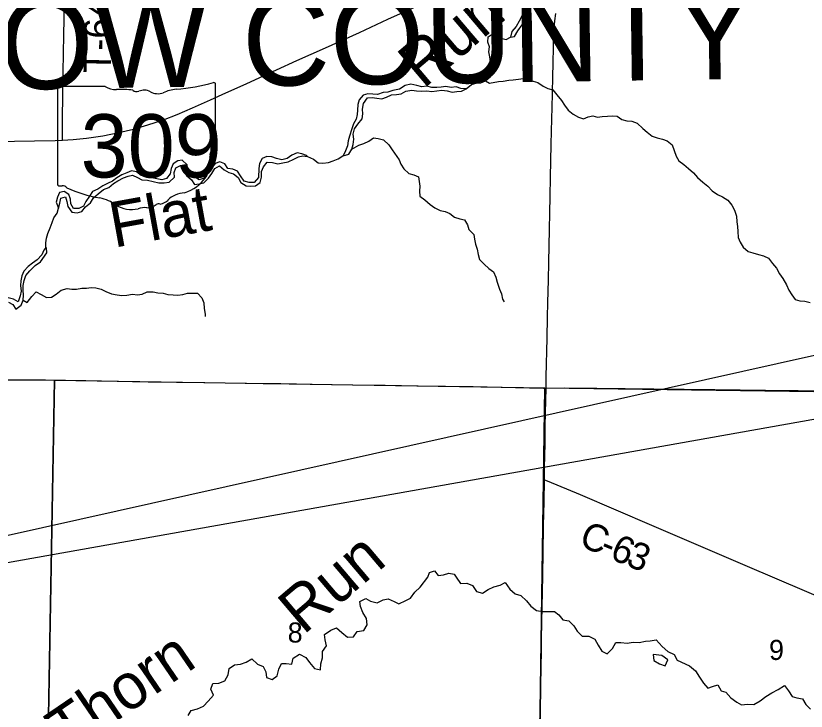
# Model space of a CAD drawing. Extents: x 0 to 45.9, y 0 to 22.
# Drawn here: x 6.459 to 8.107, y 18.033 to 19.483 of the extents above; entities that cross this region are included whole.
import ezdxf

# ---------------------------------------------------------------- set-up
doc = ezdxf.new("R2010")
doc.units = 0
for name, color, linetype in [('GM_X_County_Road', 7, 'Continuous'), ('GM_X_County_Road_Text', 7, 'Continuous'), ('GM_X_County_Text', 7, 'Continuous'), ('GM_X_Minor_Lake', 7, 'Continuous'), ('GM_X_Minor_River', 7, 'Continuous'), ('GM_X_Minor_River_Text', 7, 'Continuous'), ('GM_X_Section', 7, 'Continuous'), ('GM_X_Section_Text', 7, 'Continuous'), ('GM_X_State_Location', 7, 'Continuous'), ('GM_X_State_Route', 7, 'Continuous'), ('GM_X_State_Shield', 7, 'Continuous'), ('GM_X_Township_Road', 7, 'Continuous'), ('GM_X_Township_Road_Text', 7, 'Continuous'), ('SH_Border', 7, 'Continuous')]:
    doc.layers.add(name, color=color, linetype=linetype)

msp = doc.modelspace()

# ---------------------------------------------------------------- linework, layer by layer
at = {"layer": 'GM_X_County_Road'}
for points in [[(7.5646, 18.7065), (7.5647, 18.7113), (7.5647, 18.73), (7.5668, 18.8107), (7.5676, 18.8542), (7.5681, 18.8852), (7.5693, 18.9318), (7.5702, 18.9691), (7.571, 19.0032), (7.5733, 19.1058), (7.574, 19.1461), (7.5745, 19.1803), (7.5753, 19.2145), (7.576, 19.2424), (7.5772, 19.2921), (7.5777, 19.3201), (7.5783, 19.3575), (7.5793, 19.3821), (7.5801, 19.4194), (7.5807, 19.4411), (7.5814, 19.4566), (7.5828, 19.4721), (7.5847, 19.4875)], [(6.2851, 18.7249), (6.3844, 18.7247), (6.5212, 18.7234), (6.6051, 18.7221), (6.7354, 18.7198), (6.8535, 18.7178), (6.9374, 18.7166), (6.9747, 18.7162), (7.012, 18.7157), (7.0772, 18.7145), (7.1611, 18.7135), (7.2295, 18.7125), (7.2979, 18.7112), (7.4129, 18.7096), (7.5589, 18.7064), (7.5646, 18.7065)], [(7.5612, 18.5152), (7.5616, 18.5404), (7.5628, 18.5901), (7.563, 18.6276), (7.5642, 18.6807), (7.5646, 18.7065)], [(7.5646, 18.7065), (7.6024, 18.707), (7.6707, 18.7061), (7.7889, 18.705), (7.9163, 18.7034), (8.0219, 18.7023), (8.0903, 18.7015), (8.1929, 18.7), (8.2363, 18.6995), (8.3078, 18.6991), (8.4353, 18.6974), (8.4943, 18.6963), (8.5313, 18.6958)], [(7.5458, 17.698), (7.5463, 17.7142), (7.5476, 17.7856), (7.5486, 17.8446), (7.5508, 17.9503), (7.5522, 18.0404), (7.5541, 18.1211), (7.5547, 18.1615), (7.5549, 18.1832), (7.5556, 18.2174), (7.5564, 18.2516), (7.557, 18.2795), (7.5577, 18.3168), (7.5585, 18.3633), (7.5593, 18.4193), (7.5603, 18.469), (7.5612, 18.5152)], [(7.5612, 18.5152), (7.5666, 18.5129), (7.6355, 18.4843), (7.7843, 18.4208), (7.9787, 18.3375), (8.1074, 18.2827), (8.1417, 18.268), (8.2218, 18.2337), (8.296, 18.2014), (8.3105, 18.1959), (8.3195, 18.1935), (8.3287, 18.192), (8.3442, 18.191), (8.4873, 18.1896), (8.5278, 18.189), (8.5332, 18.1889)]]:
    msp.add_lwpolyline(points, dxfattribs=at)
at = {"layer": 'GM_X_Minor_Lake'}
for points in [[(7.7875, 18.1513), (7.789, 18.1384), (7.8008, 18.1313), (7.813, 18.1275), (7.8157, 18.1337)], [(7.8157, 18.1337), (7.8186, 18.1401), (7.8061, 18.1487), (7.7875, 18.1513)]]:
    msp.add_lwpolyline(points, dxfattribs=at)
at = {"layer": 'GM_X_Minor_River'}
for points in [[(7.5153, 19.4844), (7.5085, 19.4713), (7.5022, 19.4605), (7.4935, 19.4497), (7.4902, 19.438)], [(7.4902, 19.438), (7.4986, 19.4397), (7.5057, 19.4512), (7.5144, 19.4635), (7.5196, 19.4733), (7.5263, 19.4837)], [(7.3978, 19.3304), (7.4091, 19.3396), (7.419, 19.3424), (7.4285, 19.3428), (7.4381, 19.3468), (7.4485, 19.3563), (7.4507, 19.3665), (7.4522, 19.3775), (7.449, 19.3875), (7.4474, 19.397), (7.445, 19.4073), (7.4465, 19.4179), (7.4429, 19.4275), (7.4436, 19.4389), (7.4541, 19.4458), (7.4639, 19.4467), (7.4704, 19.4363), (7.4813, 19.4333), (7.4902, 19.438)], [(7.4381, 19.3468), (7.4466, 19.342), (7.4657, 19.346), (7.4752, 19.3465), (7.4866, 19.3485), (7.4961, 19.3489), (7.5071, 19.3505), (7.5166, 19.3518), (7.5275, 19.3504), (7.5377, 19.3467), (7.5474, 19.3437), (7.5582, 19.3358), (7.5683, 19.331), (7.5784, 19.3284), (7.5868, 19.3176), (7.5964, 19.3063), (7.6033, 19.2966), (7.6106, 19.2857), (7.6213, 19.2775), (7.6318, 19.2711), (7.6426, 19.2678), (7.6522, 19.2721), (7.6618, 19.2744), (7.6719, 19.2711), (7.6814, 19.2728), (7.6928, 19.2736), (7.7023, 19.2741), (7.7125, 19.2734), (7.7225, 19.2663), (7.7327, 19.2637), (7.7436, 19.2627), (7.7545, 19.259), (7.7659, 19.248), (7.7756, 19.2401), (7.7856, 19.2319), (7.7961, 19.2285), (7.8073, 19.2256), (7.8171, 19.2223), (7.8271, 19.2136), (7.8313, 19.2017), (7.8359, 19.1902), (7.8413, 19.1806), (7.8517, 19.1727), (7.8613, 19.1644), (7.8717, 19.1554), (7.8805, 19.1457), (7.8916, 19.1355), (7.9016, 19.1272), (7.9108, 19.1175), (7.9219, 19.11), (7.9324, 19.1051), (7.9432, 19.098), (7.9516, 19.0879), (7.9574, 19.0774), (7.9612, 19.0652), (7.9624, 19.0534), (7.9633, 19.0435), (7.9645, 19.0328), (7.9649, 19.0203), (7.9688, 19.0106), (7.9753, 19.0006), (7.9857, 18.9912), (7.9955, 18.9886), (8.0075, 18.9853), (8.0176, 18.9823), (8.0281, 18.9771), (8.0365, 18.9662), (8.0446, 18.9565), (8.051, 18.9445), (8.058, 18.9349), (8.0659, 18.9217), (8.0709, 18.9109), (8.0767, 18.9009), (8.084, 18.8912), (8.0938, 18.8887), (8.104, 18.8876), (8.1153, 18.8846)], [(7.3978, 19.3304), (7.3869, 19.3311), (7.3771, 19.3344), (7.3669, 19.3335), (7.3559, 19.335), (7.3461, 19.3337), (7.3366, 19.3329), (7.3267, 19.3331), (7.3158, 19.3361), (7.3059, 19.3349), (7.295, 19.3371), (7.2826, 19.3401), (7.2708, 19.3373), (7.2588, 19.3297), (7.2451, 19.3267), (7.2344, 19.3235), (7.225, 19.323), (7.2135, 19.3188), (7.2033, 19.3195), (7.1931, 19.3201), (7.1831, 19.3174), (7.1753, 19.3077), (7.1724, 19.2979), (7.1713, 19.2862), (7.1706, 19.2767), (7.1685, 19.2669), (7.1629, 19.2572), (7.16, 19.247), (7.155, 19.2315), (7.1521, 19.2217), (7.1507, 19.2115), (7.1462, 19.201), (7.1418, 19.1909)], [(7.1418, 19.1909), (7.1536, 19.194), (7.1596, 19.2044), (7.1625, 19.2146), (7.1639, 19.2256), (7.1627, 19.2359), (7.1653, 19.2468), (7.172, 19.2569), (7.1814, 19.268), (7.1824, 19.2783), (7.182, 19.2882), (7.1842, 19.2995), (7.1921, 19.3118), (7.2019, 19.3123), (7.2117, 19.3109), (7.2219, 19.3098), (7.2322, 19.313), (7.2426, 19.318), (7.2525, 19.3185), (7.2624, 19.3201), (7.2723, 19.3252), (7.2845, 19.3279), (7.2947, 19.326), (7.3057, 19.3257), (7.3159, 19.3262), (7.3265, 19.3248), (7.3371, 19.3264), (7.3474, 19.3276), (7.3583, 19.3262), (7.3689, 19.3236), (7.3788, 19.3249), (7.3882, 19.3254), (7.3978, 19.3304)], [(7.1596, 19.2044), (7.1742, 19.2132), (7.1845, 19.2167), (7.1949, 19.2213), (7.2045, 19.2279), (7.2147, 19.2268), (7.2256, 19.2239), (7.2367, 19.2133), (7.2436, 19.2029), (7.2582, 19.1827), (7.2621, 19.1731), (7.2683, 19.1634), (7.2782, 19.1537), (7.2887, 19.1511), (7.2988, 19.1466), (7.3001, 19.1371), (7.3013, 19.1272), (7.3007, 19.117), (7.3015, 19.1067), (7.3119, 19.0992), (7.323, 19.089), (7.333, 19.0823), (7.3435, 19.077), (7.354, 19.0748), (7.3642, 19.0704), (7.3738, 19.0629), (7.3847, 19.0595), (7.3948, 19.057), (7.4006, 19.0469), (7.4037, 19.037), (7.4141, 19.0268), (7.4153, 19.0169), (7.4177, 19.0066), (7.4208, 18.9959), (7.4231, 18.9852), (7.4259, 18.9745), (7.4355, 18.9647), (7.4451, 18.9561), (7.4547, 18.949), (7.4597, 18.9374), (7.4628, 18.9271), (7.4674, 18.9129), (7.4713, 18.9033), (7.4736, 18.8922), (7.4772, 18.8864)], [(7.0675, 19.1895), (7.0649, 19.1911), (7.0552, 19.1952), (7.0454, 19.197), (7.0346, 19.192), (7.025, 19.1854), (7.0139, 19.1827), (7.003, 19.1852), (6.9932, 19.1885), (6.9827, 19.1892), (6.9727, 19.1853), (6.9675, 19.1744), (6.9657, 19.1646), (6.9652, 19.1453), (6.9558, 19.1353), (6.9459, 19.1348), (6.9354, 19.1381), (6.9274, 19.149), (6.9212, 19.1586), (6.9115, 19.1627), (6.9013, 19.1641), (6.8951, 19.1738), (6.8846, 19.1779), (6.8751, 19.1747), (6.8669, 19.1651), (6.8519, 19.1442), (6.8416, 19.1407), (6.8315, 19.1467), (6.8218, 19.1523), (6.8149, 19.162), (6.8163, 19.1718), (6.8063, 19.1816), (6.7968, 19.1803), (6.7872, 19.1741), (6.7828, 19.164), (6.7813, 19.1534), (6.7731, 19.1437), (6.7636, 19.141), (6.7425, 19.1446), (6.7316, 19.1476), (6.7206, 19.1498), (6.7106, 19.1576), (6.7004, 19.1591), (6.6909, 19.1551), (6.6801, 19.1509), (6.6701, 19.1451), (6.6605, 19.1381), (6.6505, 19.1331), (6.6409, 19.1284), (6.6301, 19.1215), (6.6194, 19.1165), (6.613, 19.1068), (6.6055, 19.0956), (6.6007, 19.0858), (6.5903, 19.0808), (6.5797, 19.0811), (6.5743, 19.0908), (6.5731, 19.1003), (6.5696, 19.1099), (6.5599, 19.1162), (6.5504, 19.1142), (6.5459, 19.1045), (6.5434, 19.0943), (6.5483, 19.0816)], [(6.5483, 19.0816), (6.5509, 19.0922), (6.5534, 19.1023), (6.563, 19.1055), (6.5657, 19.0952), (6.5677, 19.0849), (6.5761, 19.0736), (6.5871, 19.0718), (6.5966, 19.0746), (6.6044, 19.0842), (6.6149, 19.0927), (6.6209, 19.1031), (6.6306, 19.1116), (6.6422, 19.1204), (6.6529, 19.125), (6.6626, 19.1331), (6.6722, 19.1389), (6.6834, 19.1447), (6.6933, 19.1482), (6.7028, 19.1503), (6.7126, 19.1458), (6.7223, 19.1406), (6.7336, 19.1399), (6.7457, 19.1369), (6.7577, 19.1343), (6.7683, 19.1344), (6.779, 19.136), (6.7898, 19.1459), (6.7897, 19.1562), (6.7927, 19.166), (6.8026, 19.1703), (6.8095, 19.1595), (6.8153, 19.1498), (6.8257, 19.1408), (6.8318, 19.1311), (6.8417, 19.1323), (6.8512, 19.1344), (6.8606, 19.1444), (6.8677, 19.154), (6.874, 19.1641), (6.884, 19.1699), (6.8937, 19.1613), (6.9033, 19.1557), (6.9131, 19.1535), (6.9228, 19.1457), (6.9285, 19.1349), (6.9393, 19.1281), (6.9491, 19.1275), (6.959, 19.1283), (6.9687, 19.1349), (6.9712, 19.1459), (6.9712, 19.158), (6.9756, 19.1681), (6.9835, 19.1778), (6.9944, 19.1771), (7.0053, 19.1742), (7.0156, 19.1758), (7.0267, 19.1781), (7.0386, 19.1839), (7.0482, 19.1885), (7.0577, 19.1909), (7.0675, 19.1895)], [(7.0675, 19.1895), (7.0795, 19.1835), (7.0895, 19.1764), (7.0993, 19.1753), (7.1107, 19.1766), (7.1207, 19.1805), (7.131, 19.1843), (7.1406, 19.1909), (7.1418, 19.1909)], [(6.5218, 18.9995), (6.5221, 19.0094), (6.5231, 19.0192), (6.526, 19.029), (6.5309, 19.0403), (6.535, 19.0516), (6.5387, 19.0614), (6.5454, 19.0714), (6.5483, 19.0816)], [(6.5218, 18.9995), (6.5179, 18.9939), (6.5138, 18.9842), (6.5041, 18.9742), (6.4944, 18.9672), (6.4847, 18.9599), (6.4758, 18.9503), (6.4721, 18.9405), (6.4699, 18.9303), (6.4689, 18.9201), (6.4701, 18.9087), (6.4687, 18.8988), (6.4642, 18.8864), (6.4545, 18.892), (6.4436, 18.8946), (6.4328, 18.8907), (6.4214, 18.8868), (6.4102, 18.8928)], [(6.4437, 18.8858), (6.4534, 18.881), (6.4596, 18.8713), (6.4704, 18.8794), (6.4749, 18.8899), (6.4755, 18.9005), (6.4747, 18.9108), (6.4749, 18.9203), (6.4764, 18.9309), (6.4801, 18.941), (6.4887, 18.9507), (6.4999, 18.9618), (6.5108, 18.9694), (6.5242, 18.9888), (6.5233, 18.9987), (6.5218, 18.9995)], [(6.4749, 18.8899), (6.4831, 18.8851), (6.4925, 18.8974), (6.5019, 18.9074), (6.5119, 18.9014), (6.5231, 18.895), (6.5337, 18.8959), (6.5434, 18.9024), (6.5535, 18.9109), (6.5664, 18.9143), (6.5762, 18.9129), (6.5861, 18.913), (6.5971, 18.9146), (6.6066, 18.9151), (6.6161, 18.9164), (6.6263, 18.9157), (6.6372, 18.9128), (6.6469, 18.9075), (6.6589, 18.903), (6.6702, 18.9008), (6.6804, 18.8994), (6.6906, 18.9003), (6.7028, 18.9026), (6.7126, 18.9008), (6.7225, 18.902), (6.7329, 18.9074), (6.7457, 18.9071), (6.7555, 18.9053), (6.7661, 18.9042), (6.7759, 18.9013), (6.7872, 18.9006), (6.7971, 18.9004), (6.8077, 18.9016), (6.8172, 18.9044), (6.8279, 18.9044), (6.8377, 18.9042), (6.8473, 18.8948), (6.8512, 18.8844), (6.852, 18.8722), (6.8543, 18.8608), (6.8542, 18.8558)], [(7.318, 18.3124), (7.3219, 18.3221), (7.3322, 18.3252), (7.3399, 18.3155), (7.3505, 18.3171), (7.362, 18.3206), (7.3729, 18.3188), (7.3772, 18.3121)], [(7.1629, 18.1879), (7.1709, 18.1993), (7.1845, 18.2009), (7.1917, 18.2131), (7.1905, 18.2263), (7.1825, 18.2388), (7.1779, 18.2509), (7.1763, 18.2612), (7.1888, 18.268), (7.1987, 18.2624), (7.2124, 18.259), (7.2253, 18.2651), (7.2351, 18.2671), (7.248, 18.2618), (7.2579, 18.2565), (7.2719, 18.2638), (7.2818, 18.2687), (7.2912, 18.2809), (7.3018, 18.2912), (7.318, 18.3124)], [(7.3772, 18.3121), (7.386, 18.2987), (7.3996, 18.2995), (7.4114, 18.2946), (7.4194, 18.2825), (7.432, 18.2787), (7.4437, 18.2867), (7.4558, 18.2924), (7.4687, 18.2955), (7.4793, 18.3012), (7.4892, 18.2873), (7.4999, 18.2778), (7.512, 18.2741), (7.5238, 18.2631), (7.5326, 18.2521), (7.5444, 18.2427), (7.558, 18.2408), (7.5819, 18.2409), (7.5914, 18.2334), (7.5994, 18.2235), (7.612, 18.2213), (7.6226, 18.2107), (7.6295, 18.1994), (7.6401, 18.1895), (7.6538, 18.1892), (7.666, 18.1828), (7.6732, 18.1707), (7.6808, 18.1578), (7.6922, 18.1525), (7.7032, 18.1636), (7.71, 18.1761), (7.7206, 18.1758), (7.7339, 18.1743), (7.7464, 18.177), (7.7585, 18.1759), (7.7718, 18.179), (7.7817, 18.1794), (7.7942, 18.1813), (7.8067, 18.1677), (7.8182, 18.1571), (7.8315, 18.1507), (7.838, 18.139), (7.8638, 18.1277), (7.876, 18.1167), (7.8847, 18.1039), (7.8924, 18.091), (7.9015, 18.0808), (7.9117, 18.0846), (7.9223, 18.0877), (7.9292, 18.0752), (7.9391, 18.0722), (7.9498, 18.0605), (7.9623, 18.0514), (7.9718, 18.0458), (7.9847, 18.0477), (7.9976, 18.047), (8.0108, 18.0546), (8.0226, 18.0634), (8.0354, 18.0714), (8.0483, 18.0782), (8.0612, 18.0866), (8.0699, 18.0753), (8.0776, 18.0632), (8.0871, 18.0605), (8.0992, 18.0587), (8.1057, 18.047), (8.116, 18.0371)], [(6.8183, 18.024), (6.8251, 18.0343), (6.838, 18.0374), (6.8505, 18.0431), (6.8603, 18.0534), (6.8713, 18.0659), (6.8655, 18.0788), (6.8697, 18.0902), (6.8826, 18.0914), (6.8947, 18.096), (6.9018, 18.1089), (6.9037, 18.1218), (6.915, 18.1298), (6.9276, 18.1306), (6.9397, 18.1352), (6.951, 18.1417), (6.9628, 18.1307), (6.975, 18.1262), (6.9807, 18.1152), (6.9815, 18.1027), (6.9933, 18.0986), (7.0039, 18.1066), (7.0073, 18.1203), (7.0129, 18.132), (7.0228, 18.1321), (7.0349, 18.1306), (7.0375, 18.1431), (7.0508, 18.1519), (7.0637, 18.1447), (7.0717, 18.1341), (7.082, 18.1217), (7.0945, 18.1187), (7.0949, 18.1316), (7.0982, 18.1441), (7.0986, 18.157), (7.1069, 18.1692), (7.1038, 18.1813), (7.103, 18.193), (7.1162, 18.2014), (7.128, 18.2068), (7.139, 18.1966), (7.1508, 18.1871), (7.1629, 18.1879)]]:
    msp.add_lwpolyline(points, dxfattribs=at)
at = {"layer": 'GM_X_Section'}
for points in [[(5.4871, 18.7066), (6.0626, 18.725), (6.54, 18.7231), (6.5217, 17.7114), (6.0871, 17.7131), (5.4835, 17.7031)], [(6.54, 18.7231), (7.5622, 18.7071), (7.5472, 17.6966), (6.5217, 17.7114)], [(7.5622, 18.7071), (8.5306, 18.6937), (8.5357, 17.6824), (7.5472, 17.6966)]]:
    msp.add_lwpolyline(points, close=True, dxfattribs=at)
at = {"layer": 'GM_X_State_Route'}
for points in [[(6.8649, 19.3074), (6.8896, 19.3186), (6.9406, 19.3416), (7.0029, 19.3699), (7.0452, 19.3894), (7.1047, 19.4162), (7.1755, 19.4482), (7.2349, 19.4754), (7.3, 19.505), (7.399, 19.55), (7.4519, 19.5741)], [(6.2899, 19.2184), (6.498, 19.2217), (6.5415, 19.2227), (6.5563, 19.2235), (6.5788, 19.2247), (6.6067, 19.2276), (6.6405, 19.2326), (6.6742, 19.2391), (6.7044, 19.2463), (6.7343, 19.255), (6.7668, 19.2657), (6.7959, 19.2768), (6.8273, 19.2905), (6.8649, 19.3074)]]:
    msp.add_lwpolyline(points, dxfattribs=at)
at = {"layer": 'GM_X_State_Shield'}
for p, q in [((6.5459, 19.3316), (6.5459, 19.1315)), ((6.6457, 19.335), (6.5492, 19.335)), ((6.8755, 19.2353), (6.8755, 19.34)), ((6.8755, 19.2353), (6.8755, 19.2353))]:
    msp.add_line(p, q, dxfattribs=at)
for centre, major_axis, start_param, end_param in [((6.7581, 19.6079), (0.3495, 0), 4.814394, 5.042369), ((6.8719, 19.3404), (0.00367, 0), 6.141152, 7.989035), ((6.5497, 19.332), (0.00382, 0), 1.712693, 3.28349), ((6.6687, 19.3583), (0.037, 0), 4.042523, 4.731795), ((6.681, 19.2227), (0.133, 0), 1.404758, 1.657858), ((6.7111, 19.3331), (0.0107, 0), 3.836095, 5.185415), ((6.7268, 19.3099), (0.0222, 0), 0.950623, 2.079405), ((6.8027, 19.2739), (0.0703, 0), 1.699011, 2.107814), ((6.7555, 19.3416), (0.0267, 0), 4.081561, 5.145723), ((6.8747, 19.2276), (0.00568, 0), 1.883978, 3.671073), ((6.8716, 19.2349), (0.00393, 0), 5.05454, 6.418171), ((6.8385, 19.2144), (0.0341, 0), 5.934695, 6.695948), ((6.8887, 19.1915), (0.0248, 0), 2.387724, 3.262537), ((6.7777, 19.1782), (0.0874, 0), 5.101752, 6.440018), ((6.5497, 19.131), (0.00385, 0), 3.00124, 4.508301), ((6.5503, 19.1515), (0.0294, 0), 4.665946, 4.897461), ((6.5563, 19.1199), (0.0106, 0), 0.519207, 1.627899), ((6.6902, 19.2997), (0.2524, 0), 4.195997, 4.488961), ((6.8145, 19.0753), (0.0479, 0), 1.647645, 2.488434), ((6.6149, 19.0416), (0.079, 0), 0.823519, 1.323587), ((6.7539, 19.1121), (0.0282, 0), 4.937069, 5.64225), ((6.7003, 19.1189), (0.0501, 0), 4.026481, 4.996735), ((6.7293, 19.0497), (0.0412, 0), 1.495662, 1.94098), ((6.7329, 19.1039), (0.0267, 0), 4.691044, 5.507374), ((6.7571, 19.0846), (0.00752, 0), 1.147584, 2.315152)]:
    msp.add_ellipse(centre, major_axis=major_axis, ratio=0.8, start_param=start_param, end_param=end_param, dxfattribs=at)
at = {"layer": 'GM_X_Township_Road'}
msp.add_lwpolyline([(6.5563, 19.2235), (6.5564, 19.2318), (6.5569, 19.2753), (6.5572, 19.3094), (6.5581, 19.3654), (6.5593, 19.443), (6.5605, 19.5082), (6.5618, 19.5859), (6.5633, 19.6636), (6.5655, 19.7101), (6.5652, 19.7172), (6.5649, 19.7189), (6.5645, 19.721), (6.564, 19.7226), (6.5634, 19.724)], dxfattribs=at)
at = {"layer": 'SH_Border'}
msp.add_lwpolyline([(9.5057, 19.0827), (5.2104, 18.1241), (9.5057, 18.8875)], close=True, dxfattribs=at)

# ---------------------------------------------------------------- texts
at = {"layer": 'GM_X_County_Road_Text'}
for s, rotation, p in [('C', 336.8562, (7.6305, 18.3792)), ('6', 337.0732, (7.6951, 18.3516)), ('3', 338.0091, (7.7283, 18.3376)), ('-', 336.8964, (7.6735, 18.3609))]:
    msp.add_text(s, height=0.0568, rotation=rotation, dxfattribs=at).set_placement(p)
at = {"layer": 'GM_X_County_Text'}
msp.add_text('MORROW COUNTY', height=0.189394, rotation=0.8203, dxfattribs=at).set_placement((5.6522, 19.3177))
at = {"layer": 'GM_X_Minor_River_Text'}
for s, rotation, p in [('Run', 40.3114, (7.3085, 19.3288)), ('Flat', 10.3153, (6.6638, 18.9989)), ('Run', 40.3115, (7.0586, 18.1905)), ('Thorn', 34.3127, (6.5666, 17.9416))]:
    msp.add_text(s, height=0.09472, rotation=rotation, dxfattribs=at).set_placement(p)
at = {"layer": 'GM_X_Section_Text'}
for s, p in [('8', (7.026, 18.1759)), ('9', (8.0293, 18.1396))]:
    msp.add_text(s, height=0.0419, rotation=0, dxfattribs=at).set_placement(p)
at = {"layer": 'GM_X_State_Location'}
for s in ['s', 'r']:
    msp.add_text(s, height=0.000189, dxfattribs=at).set_placement((6.707, 19.2182))
msp.add_text('309', height=0.000189, rotation=0, dxfattribs=at).set_placement((6.6402, 19.2044))
at = {"layer": 'GM_X_State_Shield'}
msp.add_text('309', height=0.13184, dxfattribs=at).set_placement((6.5944, 19.1456))
at = {"layer": 'GM_X_Township_Road_Text'}
msp.add_text('T-64', height=0.05682, rotation=88.9333, dxfattribs=at).set_placement((6.6571, 19.363))

doc.saveas('drawing.dxf')
